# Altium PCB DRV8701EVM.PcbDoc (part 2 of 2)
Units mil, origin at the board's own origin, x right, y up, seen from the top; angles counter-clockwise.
Board outline 3500 x 2200 mil, 2 copper layers (Top Layer, Bottom Layer), stack 64.8 mil thick; 118 components, 65 nets, 313 pads, 397 vias.
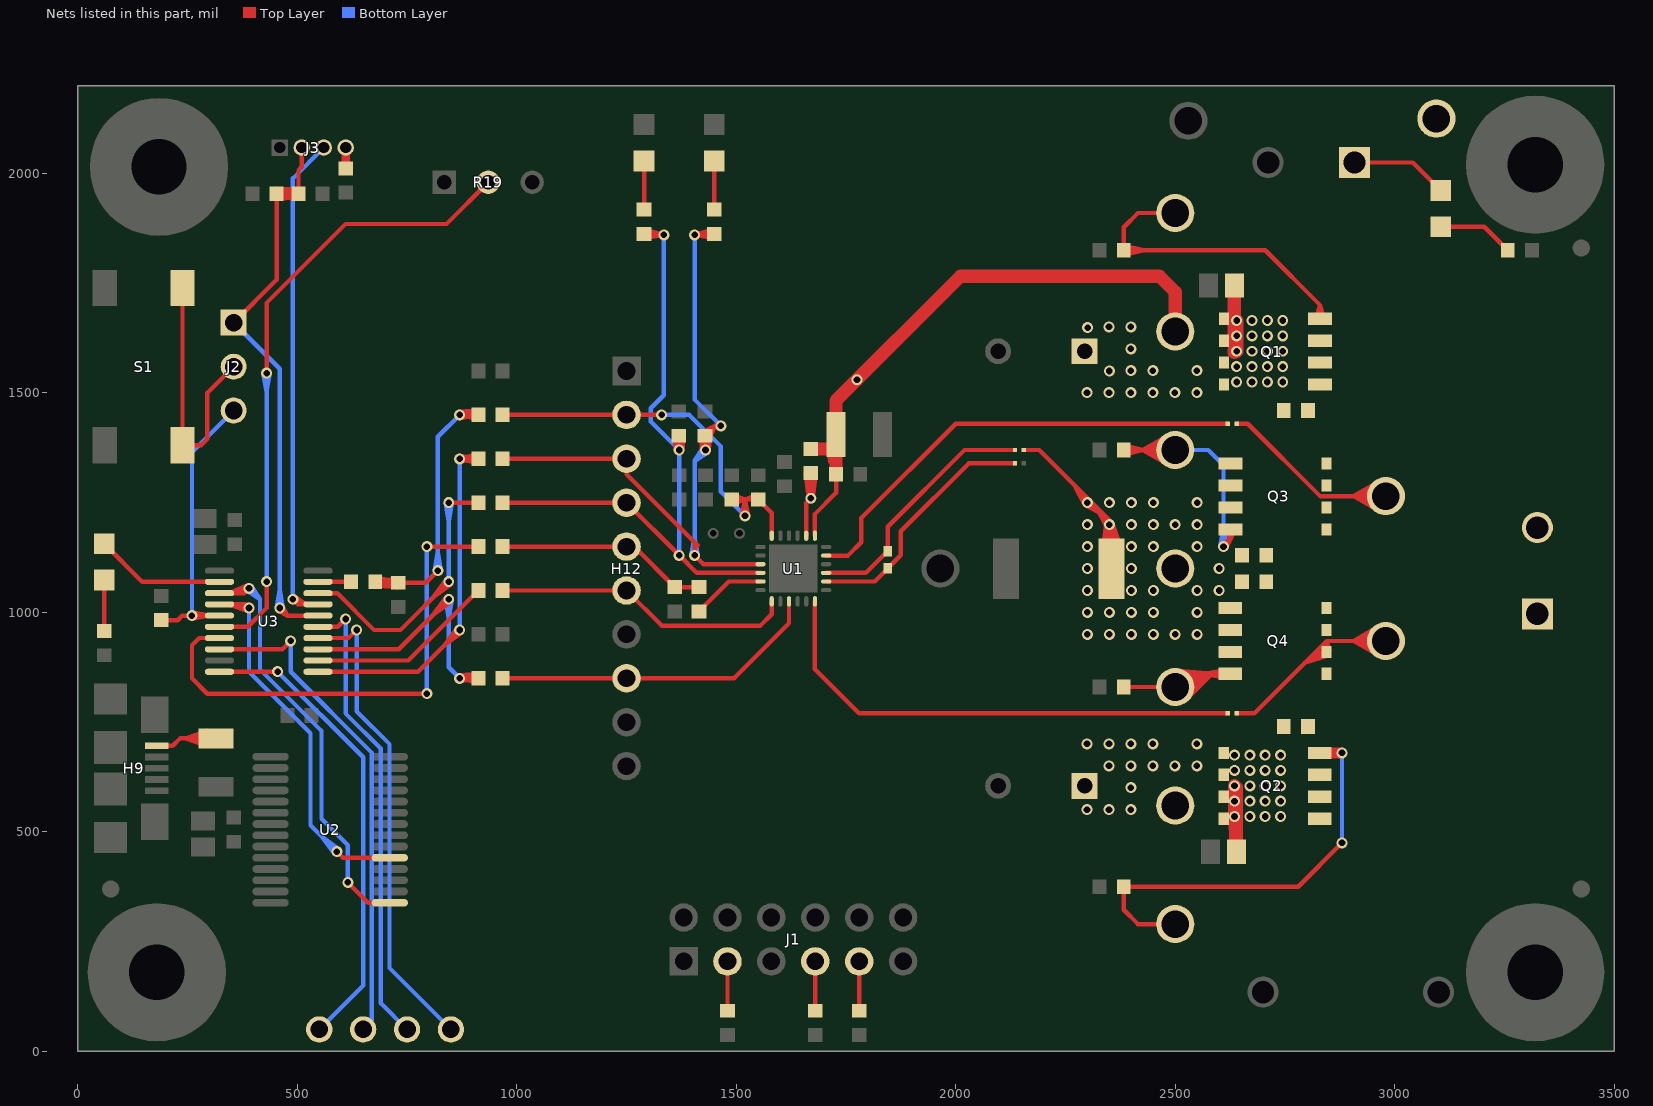
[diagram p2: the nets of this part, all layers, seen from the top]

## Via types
v1: diameter 25, hole 15, Top Layer to Bottom Layer, tented both sides, 392 vias
v2: diameter 20, hole 8, Top Layer to Bottom Layer, 5 vias

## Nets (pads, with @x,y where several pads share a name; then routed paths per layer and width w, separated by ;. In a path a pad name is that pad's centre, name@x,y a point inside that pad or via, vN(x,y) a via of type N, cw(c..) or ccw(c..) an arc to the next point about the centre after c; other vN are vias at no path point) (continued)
NetC13_2: C13.2 C14.2 NT3.1 Q3.1 Q3.2 Q3.3 Q4.1 Q4.2 Q4.3 R9.2 TP12.1 | length 1895.3
  Top Layer w10: NT3.1@2155,1370 2190,1370 2355.08,1204.92 R9.2@2355.08,1100 ; v1@2293.65,1246 2271,1289 ; v1@2296.04,1243.63 2338.22,1221.78 ; v1@2304.92,1255.66 2338.22,1221.78 ; v1@2305.66,1254.93 2271,1289 ; R9.2@2331.08,1144.42 v1@2355.08,1198.9 ; R9.2@2340.66,1141.14 v1@2355.08,1198.9 ; v1@2342.51,1200.29 R9.2@2344.56,1156.78 ; v1@2342.67,1201.59 R9.2@2337.04,1157.96 ; v1@2343.2,1196.83 R9.2@2365.12,1158.7 ; v1@2343.66,1195.99 2320.81,1239.19 ; v1@2343.78,1195.81 R9.2@2371.81,1160.93 ; R9.2@2355.08,1139.37 v1@2355.08,1198.9 ; v1@2355.65,1204.93 2320.81,1239.19 ; v1@2356.83,1203.09 R9.2@2371.81,1160.93 ; v1@2356.95,1197.19 R9.2@2337.04,1157.96 ; v1@2357.24,1201.97 R9.2@2365.12,1158.7 ; v1@2357.33,1198.43 R9.2@2344.56,1156.78 ; R9.2@2369.5,1141.14 v1@2355.08,1198.9 ; R9.2@2379.08,1144.42 v1@2355.08,1198.9 ; 2271,1289 v1(2300,1250) 2338.22,1221.78 ; 2320.81,1239.19 v1(2350,1200) ; R9.2@2337.04,1157.96 v1(2350,1200) ; R9.2@2344.56,1156.78 v1(2350,1200) ; v1(2350,1200) R9.2@2355.08,1156.94 ; v1(2350,1200) R9.2@2371.81,1160.93 ; v1(2350,1200) R9.2@2365.12,1158.7 ; v1(2350,1200) R9.2@2355.08,1156.81 ; R9.2@2355.08,1156.81 2357.5,1200.23 R9.2@2355.08,1156.94 ; R9.2@2355.08,1156.81 2342.65,1198.49 R9.2@2355.08,1156.94
  other v1: 2300,950 2350,950 2400,950 2450,950 2500,950 2550,950 2300,1000 2350,1000 2400,1000 2450,1000 2550,1000 2300,1050 2400,1050 2450,1050 2550,1050 2600,1050 2300,1100 2400,1100 2600,1100 2300,1150 2400,1150 2450,1150 2550,1150 2300,1200 2400,1200 2450,1200 2500,1200 2550,1200 2350,1250 2400,1250 2450,1250 2550,1250
NetD1_2: D1.2 R23.2 | length 116.1
  Top Layer w10: R23.2@60,957.56 D1.2@60,1073.66
NetD2_2: D2.2 R24.2 | length 111.1
  Top Layer w10: R24.2@1450,1917.56 D2.2@1450,2028.66
NetD3_2: D3.2 R25.2 | length 111.1
  Top Layer w10: R25.2@1290,1917.56 D3.2@1290,2028.66
NetD4_2: D4.2 R26.2 | length 174.7
  Top Layer w10: D4.2@3105,1878.66 3203.78,1878.66 R26.2@3257.44,1825
NetF1_1: F1.1 H9.1 | length 421.9
  Top Layer w10: H9.1@180,696.18 216.18,696.18 ; H9.1@198.7,696.18 216.18,696.18 ; F1.1@294.58,695.74 245,713 ; F1.1@294.58,730.26 245,713 ; F1.1@296.96,705.52 245,713 ; F1.1@296.96,720.48 245,713 ; F1.1@297.5,713 245,713 ; F1.1@315,713 233,713 216.18,696.18
NetJ1_3: J1.3 R13.1 | length 112.4
  Top Layer w10: R13.1@1480,92.56 J1.3@1480,205
NetJ1_7: J1.7 R27.2 | length 112.4
  Top Layer w10: R27.2@1680,92.56 J1.7@1680,205
NetJ1_9: J1.9 R28.2 | length 112.4
  Top Layer w10: R28.2@1780,92.56 J1.9@1780,205
NetJ2_2: J2.2 S1.1 S1.2 | length 610.4
  Top Layer w10: S1.1@238.58,1739.13 S1.2@238.58,1380.87 280.87,1380.87 295,1395 295,1500 J2.2@355,1560
NetJ3_4: J3.4 R18.1 | length 94.9
  Top Layer w20: R18.1@610.21,2011.56 J3.4@610.21,2059 R18.1@610.21,2011.56
NetQ1_4: Q1.4 R1.1 TP5.1 | length 867.5
  Top Layer w10: R1.1@2383.82,1814.33 2428.31,1825 R1.1@2383.82,1835.67 ; TP5.1@2500,1910 2415,1910 2382.56,1877.56 R1.1@2382.56,1825 2705,1825 2829.61,1700.39 ; Q1.4@2820.72,1670.38 2829.61,1700.39 ; Q1.4@2829.61,1669.09 2829.61,1700.39 ; Q1.4@2838.49,1670.38 2829.61,1700.39
NetQ2_4: Q2.4 R2.2 TP6.1 | length 1557.5
  Top Layer w10: TP6.1@2500,290 2415,290 2382.56,322.44 R2.2@2382.56,375 2780,375 v1(2880,475) ; Q2.4@2829.3,680 v1(2880,680) ; v1@2877.51,672.93 Q2.4@2843.4,688.91 ; v1@2877.51,687.07 Q2.4@2843.4,671.09 ; v1@2879.25,672.54 Q2.4@2842.33,680 ; v1@2879.25,687.46 Q2.4@2842.33,680 ; v1@2879.34,672.53 Q2.4@2837.5,680 ; v1@2879.34,687.47 Q2.4@2837.5,680 ; v1@2881.04,672.57 Q2.4@2843.4,671.09 ; v1@2881.04,687.43 Q2.4@2843.4,688.91 ; Q2.4@2837.5,680 v1(2880,680) ; Q2.4@2842.33,680 v1(2880,680) ; Q2.4@2842.33,680 v1(2880,680) ; Q2.4@2843.4,671.09 v1(2880,680) ; Q2.4@2843.4,671.09 v1(2880,680) ; Q2.4@2843.4,688.91 v1(2880,680) ; Q2.4@2843.4,688.91 v1(2880,680)
  Bottom Layer w10: v1(2880,475) v1(2880,680)
NetQ3_4: Q3.4 R3.1 TP9.1 | length 1425.2
  Top Layer w10: R3.1@2382.56,1370 TP9.1@2500,1370 2426.5,1370 ; R3.1@2383.82,1359.33 2428.31,1370 R3.1@2383.82,1380.67 ; TP9.1@2489.92,1332.84 2426.5,1370 ; TP9.1@2489.92,1407.16 2426.5,1370 ; TP9.1@2494.47,1342.04 2426.5,1370 ; TP9.1@2494.47,1397.96 2426.5,1370 ; TP9.1@2497.67,1351.65 2426.5,1370 ; TP9.1@2497.67,1388.35 2426.5,1370 ; TP9.1@2499.51,1361.51 2426.5,1370 ; TP9.1@2499.51,1378.49 2426.5,1370 ; v1@2605.65,1156.11 2626,1166 ; v1(2610,1150) 2626,1166 ; v1@2616.11,1145.65 2626,1166 ; Q3.4@2617.19,1187.35 2626,1166 ; Q3.4@2634.81,1187.35 2626,1166 ; 2626,1166 Q3.4@2626,1189.09 2626,1166
  Bottom Layer w10: TP9.1@2500,1370 2575,1370 2610,1335 v1(2610,1150) ; v1@2602.53,1150.66 2610,1192.5 v1@2617.47,1150.66
NetQ4_4: Q4.4 R4.2 TP10.1 | length 1188.7
  Top Layer w10: R4.2@2382.56,830 TP10.1@2500,830 ; TP10.1@2494.81,858.02 2583.81,860 ; TP10.1@2495.17,868.2 2583.81,860 ; TP10.1@2495.61,847.97 2583.81,860 ; TP10.1@2497.52,838.13 2583.81,860 ; TP10.1@2503.24,822.14 2583.81,860 ; TP10.1@2508.01,813.32 2583.81,860 ; TP10.1@2513.78,805.05 2583.81,860 ; TP10.1@2520.51,797.42 2583.81,860 ; Q4.4@2611.75,851.07 2568.69,860 ; Q4.4@2611.75,868.93 2568.69,860 ; Q4.4@2612.67,860 2568.69,860 ; Q4.4@2625.7,860 2530,860 TP10.1@2500,830 ; TP10.1@2500,830 2583.81,860
NetR11_1: R11.1 U3.19 | length 75.4
  Top Layer w10: U3.19@547.2,1069.57 547.64,1070 R11.1@622.44,1070
NetR30_2: R30.2 U1.11 | length 168.4
  Top Layer w10: R30.2@1415,1002.44 1483.03,1070.47 U1.11@1555.2,1070.47
NFAULT: H12.3 R5.2 R14.1 R24.1 U1.9 | length 2607.7
  Top Layer w10: R14.1@967.56,1350 H12.3@1250,1350 1250,1315 1412.42,1152.58 ; 1405,1155 v1(1405,1130) 1425.16,1109.84 U1.9@1555.2,1109.84 ; v1@1422.54,1370.79 R5.2@1429.69,1402.44 ; v1@1422.55,1370.9 R5.2@1430,1401.14 ; v1@1422.69,1368.31 R5.2@1419.1,1400.56 ; v1@1423.21,1373.19 R5.2@1440.3,1400.76 ; R5.2@1423.31,1411.1 1451.26,1425 ; v1@1436.73,1373.32 R5.2@1419.1,1400.56 ; v1@1437.34,1368.46 R5.2@1440.3,1400.76 ; v1@1437.45,1370.9 R5.2@1430,1401.14 ; v1@1437.44,1370.94 R5.2@1429.69,1402.44 ; R5.2@1438.62,1396.46 1451.26,1425 ; R24.1@1447.12,1873.02 v1(1405,1860) ; R24.1@1448.3,1851.72 v1(1405,1860) ; R24.1@1449.02,1862.44 v1(1405,1860) ; R24.1@1450,1862.44 1447.56,1860 v1(1405,1860) ; R5.2@1419.1,1400.56 v1(1430,1370) ; R5.2@1419.1,1400.56 v1(1430,1370) ; R5.2@1429.69,1402.44 v1(1430,1370) ; R5.2@1429.69,1402.44 1451.26,1425 ; R5.2@1429.69,1402.44 v1(1430,1370) ; v1(1430,1370) R5.2@1430,1401.14 ; v1(1430,1370) R5.2@1440.3,1400.76 ; R5.2@1430,1401.14 R5.2@1428.7,1402.44 1451.26,1425 ; 1451.26,1425 v1(1465,1425) ; 1451.26,1425 v1@1462.95,1417.78 ; 1451.26,1425 v1@1462.95,1432.22 ; 1451.26,1425 v1(1465,1425) ; 1451.26,1425 v1@1462.95,1417.78 ; 1451.26,1425 v1@1462.95,1432.22 ; 1451.26,1425 v1(1465,1425) ; 1451.26,1425 v1@1462.95,1417.78 ; 1451.26,1425 v1@1462.95,1432.22 ; 1451.26,1425 v1(1465,1425) ; 1451.26,1425 v1@1462.95,1417.78 ; 1451.26,1425 v1@1462.95,1432.22 ; 1451.26,1425 v1(1465,1425) ; 1451.26,1425 v1@1462.95,1417.78 ; 1451.26,1425 v1@1462.95,1432.22 ; 1451.26,1425 v1(1465,1425)
  Bottom Layer w10: v1@1397.53,1130.66 1405,1172.5 v1@1412.47,1130.66 ; v1(1405,1130) 1405,1345 ; v1(1405,1860) 1405,1485 v1(1465,1425) ; v1@1424.16,1374.71 1405,1345 ; v1@1434.71,1364.16 1405,1345 ; 1405,1345 v1(1430,1370) 1405,1345
NFAULT_MCU: R14.2 U3.11 | length 1271.7
  Top Layer w10: U3.11@547.2,864.84 774.84,864.84 v1(870,960) 836.29,926.29 ; U3.11@573.78,864.84 610.67,864.84 ; v1@864.3,964.87 836.29,926.29 ; v1@874.87,954.3 836.29,926.29 ; R14.2@911.08,1339.34 v1(870,1350) ; R14.2@911.08,1360.66 v1(870,1350) ; v1(870,1350) R14.2@912.44,1350 ; v1(870,1350) R14.2@912.44,1350 ; R14.2@912.44,1350 870.66,1357.47 R14.2@912.44,1350 ; R14.2@912.44,1350 870.66,1342.53 R14.2@912.44,1350
  Bottom Layer w10: v1(870,960) v1(870,1350)
NSLEEP: H12.6 R21.1 U1.13 | length 686.5
  Top Layer w10: R21.1@967.56,1050 H12.6@1250,1050 1330,970 1555,970 1580.79,995.79 U1.13@1580.79,1025.2
NSLEEP_MCU: R21.2 U3.12 | length 468.2
  Top Layer w10: U3.12@547.2,890.43 752.87,890.43 R21.2@912.44,1050 ; U3.12@573.78,890.43 610.67,890.43
OUT1: C8.2 C14.1 H11.1 NT2.2 Q2.1 Q2.2 Q2.3 Q4.5 Q4.6 Q4.7 Q4.8 TP8.1 | length 1299.2
  Top Layer w10: NT2.2@2640,770 2680,770 2845,935 ; Q4.6@2837.79,913.53 2845,935 ; Q4.6@2841.2,913.48 2795.34,885.34 ; Q4.6@2844.3,907.64 2795.34,885.34 ; Q4.6@2844.3,912.36 2845,935 ; Q4.6@2846.67,901.46 2795.34,885.34 ; Q4.6@2850.87,913.13 2845,935 ; TP8.1@2969.92,897.84 2906.5,935 ; TP8.1@2969.92,972.16 2906.5,935 ; TP8.1@2974.47,907.04 2906.5,935 ; TP8.1@2974.47,962.96 2906.5,935 ; TP8.1@2977.67,916.65 2906.5,935 ; TP8.1@2977.67,953.35 2906.5,935 ; TP8.1@2979.51,926.51 2906.5,935 ; TP8.1@2979.51,943.49 2906.5,935 ; 2845,935 TP8.1@2980,935 2906.5,935
OUT2: C7.2 C13.1 H11.2 NT1.2 Q1.1 Q1.2 Q1.3 Q3.5 Q3.6 Q3.7 Q3.8 TP7.1 | length 1069.8
  Top Layer w10: NT1.2@2640,1430 2665,1430 2830,1265 TP7.1@2980,1265 2906.5,1265 ; TP7.1@2969.92,1227.84 2906.5,1265 ; TP7.1@2969.92,1302.16 2906.5,1265 ; TP7.1@2974.47,1237.04 2906.5,1265 ; TP7.1@2974.47,1292.96 2906.5,1265 ; TP7.1@2977.67,1246.65 2906.5,1265 ; TP7.1@2977.67,1283.35 2906.5,1265 ; TP7.1@2979.51,1256.51 2906.5,1265 ; TP7.1@2979.51,1273.49 2906.5,1265
P1.6: TP22.1 U3.14 | length 1094.5
  Top Layer w10: U3.14@547.2,941.61 616.61,941.61 v1(635,960)
  Bottom Layer w10: v1(635,960) 635,775 710,700 710,190 TP22.1@850,50
P1.7: TP23.1 U3.15 | length 1063.2
  Top Layer w10: U3.15@547.2,967.2 592.2,967.2 v1(610,985)
  Bottom Layer w10: v1(610,985) 610,770 690,690 690,110 TP23.1@750,50
P2.0: TP20.1 U3.8 | length 1140
  Top Layer w10: U3.8@322.8,916.02 466.02,916.02 v1(485,935)
  Bottom Layer w10: v1(485,935) 485,865 670,680 670,70 TP20.1@650,50
P2.2: TP21.1 U3.10 | length 1074.5
  Top Layer w10: U3.10@322.8,864.84 454.84,864.84 v1(455,865) v1@460,865
  Bottom Layer w10: v1(455,865) 650,670 650,150 TP21.1@550,50
PH/IN1: H12.8 R29.1 U1.15 | length 754.5
  Top Layer w10: R29.1@967.56,850 H12.8@1250,850 1495,850 1620.16,975.16 U1.15@1620.16,1025.2
PH/IN1_MCU: R29.2 U3.13 | length 1267.2
  Top Layer w10: U3.13@547.2,916.02 731.02,916.02 v1(845,1030) 811.29,996.29 ; U3.13@573.78,916.02 610.67,916.02 ; v1@839.3,1034.87 811.29,996.29 ; v1@849.87,1024.3 811.29,996.29 ; v1@868.76,857.4 R29.2@911.08,860.66 ; v1@872.52,842.94 R29.2@911.08,860.66 ; R29.2@911.08,839.34 v1(870,850) ; v1(870,850) R29.2@912.44,850 ; v1(870,850) R29.2@911.08,860.66 ; v1(870,850) R29.2@912.44,850 ; R29.2@912.44,850 870.66,857.47 R29.2@912.44,850 ; R29.2@912.44,850 870.66,842.53 R29.2@912.44,850
  Bottom Layer w10: v1@837.53,1029.34 845,987.5 ; v1@852.47,1029.34 845,987.5 ; v1(870,850) 845,875 v1(845,1030) 845,987.5
POT: R19.2 U3.6 | length 1603.2
  Top Layer w10: U3.6@322.8,967.2 387.2,967.2 430,1010 v1(430,1070) ; U3.6@349.37,967.2 386.26,967.2 ; v1(430,1545) 430,1705 610,1885 840,1885 R19.2@935,1980
  Bottom Layer w10: v1@422.53,1544.34 430,1502.5 ; v1(430,1070) v1(430,1545) 430,1502.5 ; v1@437.47,1544.34 430,1502.5
PUSH: J2.3 R15.1 U3.5 | length 837.3
  Top Layer w10: R15.1@190,982.44 227.44,982.44 237.8,992.8 v1(260,992.8) ; v1@260.66,985.32 302.5,992.8 v1@260.66,1000.27 ; v1@260.78,985.34 U3.5@296.22,992.8 ; v1@260.78,1000.26 U3.5@296.22,992.8 ; U3.5@322.8,992.8 v1(260,992.8) ; v1(260,992.8) U3.5@296.22,992.8
  Bottom Layer w10: v1(260,992.8) 260,1365 J2.3@355,1460
RESET: C22.1 J2.1 J3.2 R17.1 U3.16 | length 2092.6
  Top Layer w10: J2.1@355,1660 452.77,1757.77 C22.1@452.77,1954 ; C22.1@451.95,1942.3 R17.1@497.86,1944.18 ; C22.1@451.95,1965.71 R17.1@497.86,1963.83 ; C22.1@452.77,1953.02 R17.1@497.86,1944.18 ; C22.1@452.77,1954.99 R17.1@497.86,1963.83 ; v1@455.58,1003.94 477.2,992.8 ; C22.1@456.05,1944.76 R17.1@497.86,1963.83 ; C22.1@456.05,1963.25 R17.1@497.86,1944.18 ; v1(460,1010) 477.2,992.8 ; v1@466.06,1014.42 477.2,992.8 ; 483.74,992.8 U3.16@520.63,992.8 ; R17.1@501.39,1943.33 C22.1@456.9,1954 ; R17.1@501.39,1964.68 C22.1@456.9,1954 ; J3.2@510.21,2059 510.21,2015.21 502.65,2007.65 R17.1@502.65,1954 ; U3.16@547.2,992.8 477.2,992.8 ; C22.1@452.77,1954 R17.1@502.65,1954 ; C22.1@452.77,1954 R17.1@498.52,1954 ; C22.1@456.9,1954 R17.1@502.65,1954 ; R17.1@498.52,1954 454.03,1943.33 R17.1@498.52,1954 ; R17.1@498.52,1954 454.03,1964.68 R17.1@498.52,1954
  Bottom Layer w10: J2.1@355,1660 460,1555 v1(460,1010) ; v1@452.53,1010.66 460,1052.5 v1@467.47,1010.66
RX: U2.5 U3.4 | length 1315.1
  Top Layer w10: U3.4@322.8,1018.39 v1@381.61,1018.39 ; v1@387.83,1002.82 U3.4@349.37,1018.39 ; v1@388.08,1002.75 U3.4@343.64,1018.39 ; v1@390.74,1017.46 U3.4@343.64,1018.39 ; v1@390.85,1017.45 U3.4@349.37,1018.39 ; v1(590,455) 603.98,441.02 U2.5@710.83,441.02 ; 639.49,441.02 U2.5@678.35,441.02 ; U3.4@343.64,1018.39 v1(390,1010) ; U3.4@349.37,1018.39 v1@381.61,1018.39 ; U3.4@349.37,1018.39 v1(390,1010) ; v1@381.61,1018.39 v1(390,1010)
  Bottom Layer w10: v1(390,1010) 390,865 530,725 530,515 v1(590,455) 556.29,488.71 ; v1@584.3,450.13 556.29,488.71 ; v1@594.87,460.7 556.29,488.71
S_N: C17.2 NT4.1 U1.20 | length 609.1
  Top Layer w10: U1.20@1704.8,1070.47 1815.47,1070.47 1875,1130 1875,1185 2030,1340 NT4.1@2135,1340 2100,1340
S_P: C17.1 NT3.2 U1.21 | length 613.4
  Top Layer w10: U1.21@1704.8,1090 1795,1090 1845,1140 1845,1195 2020,1370 NT3.2@2135,1370 2100,1370
SH1: NT2.1 U1.18 | length 1171.9
  Top Layer w10: U1.18@1679.21,1025.2 1679.21,870.79 1780,770 NT2.1@2620,770 2585,770
SH2: NT1.1 U1.23 | length 1106.9
  Top Layer w10: U1.23@1704.8,1129.53 1754.53,1129.53 1785,1160 1785,1215 2000,1430 NT1.1@2620,1430 2585,1430
SNSOUT: H12.4 R7.2 R16.1 R25.1 U1.10 | length 2053.5
  Top Layer w10: R16.1@967.56,1250 H12.4@1250,1250 v1(1370,1130) 1409.69,1090.31 U1.10@1555.2,1090.31 ; R25.1@1290,1862.44 1292.44,1860 v1(1335,1860) ; R25.1@1290.98,1862.44 v1(1335,1860) ; R25.1@1291.7,1851.72 v1(1335,1860) ; R25.1@1292.88,1873.02 v1(1335,1860) ; v1@1362.54,1370.79 R7.2@1369.69,1402.44 ; v1@1362.55,1370.9 R7.2@1370,1401.14 ; v1@1362.69,1368.31 R7.2@1359.1,1400.56 ; v1@1363.21,1373.19 R7.2@1380.3,1400.76 ; R7.2@1368.7,1402.44 R7.2@1370,1401.14 ; v1@1376.73,1373.32 R7.2@1359.1,1400.56 ; v1@1377.34,1368.46 R7.2@1380.3,1400.76 ; v1@1377.45,1370.9 R7.2@1370,1401.14 ; v1@1377.44,1370.94 R7.2@1369.69,1402.44 ; R7.2@1359.1,1400.56 v1(1370,1370) ; R7.2@1359.1,1400.56 v1(1370,1370) ; R7.2@1369.69,1402.44 v1(1370,1370) ; R7.2@1369.69,1402.44 v1(1370,1370) ; v1(1370,1370) R7.2@1370,1401.14 ; v1(1370,1370) R7.2@1380.3,1400.76
  Bottom Layer w10: v1(1335,1860) 1335,1495 1305,1465 1305,1435 v1(1370,1370) v1(1370,1130)
SNSOUT_MCU: R16.2 U3.18 | length 913.4
  Top Layer w10: U3.18@547.2,1043.98 591.02,1043.98 ; U3.18@573.78,1043.98 591.02,1043.98 ; v1@839.3,1074.87 811.29,1036.29 ; v1(845,1250) R16.2@912.44,1250 ; v1@849.87,1064.3 811.29,1036.29 ; 591.02,1043.98 675,960 735,960 v1(845,1070) 811.29,1036.29
  Bottom Layer w10: v1@837.53,1249.34 845,1207.5 ; v1(845,1070) v1(845,1250) 845,1207.5 ; v1@852.47,1249.34 845,1207.5
SO: H12.5 R20.1 R30.1 R31.1 | length 485.7
  Top Layer w10: R20.1@967.56,1150 H12.5@1250,1150 1267.56,1150 R31.1@1360,1057.56 R30.1@1415,1057.56
SO_MCU: R20.2 U3.7 | length 1166.2
  Top Layer w10: U3.7@296.22,941.61 276.61,941.61 ; U3.7@322.8,941.61 276.61,941.61 ; v1(795,815) 295,815 260,850 260,925 276.61,941.61 ; v1(795,1150) R20.2@912.44,1150
  Bottom Layer w10: v1(795,815) v1(795,1150)
STATUS: D1.1 U3.2 | length 335.6
  Top Layer w10: D1.1@60,1156.34 146.77,1069.57 U3.2@322.8,1069.57 ; 259.33,1069.57 U3.2@296.22,1069.57
TEST: J3.3 U3.17 | length 1237.4
  Top Layer w10: v1@488.16,1022.73 U3.17@520.63,1018.39 ; v1@493.44,1036.66 U3.17@520.63,1018.39 ; U3.17@547.2,1018.39 501.61,1018.39 ; 501.61,1018.39 v1(490,1030) U3.17@520.63,1018.39 ; 501.61,1018.39 U3.17@520.63,1018.39
  Bottom Layer w10: v1(490,1030) 490,1988.8 J3.3@560.21,2059
TX: U2.1 U3.3 | length 1333.7
  Top Layer w10: U3.3@322.8,1043.98 378.98,1043.98 ; v1@387.4,1062.03 U3.3@349.37,1043.98 ; v1@387.65,1062.12 U3.3@344.61,1043.98 ; v1@391.18,1047.59 U3.3@344.61,1043.98 ; v1@391.31,1047.62 U3.3@349.37,1043.98 ; v1(615,385) 661.34,338.66 ; U2.1@678.35,338.66 661.34,338.66 ; U2.1@710.83,338.66 661.34,338.66 ; U3.3@344.61,1043.98 v1(390,1055) ; U3.3@349.37,1043.98 378.98,1043.98 ; U3.3@349.37,1043.98 v1(390,1055) ; 378.98,1043.98 v1(390,1055)
  Bottom Layer w10: v1@385.29,1049.16 415,1030 ; v1(390,1055) 415,1030 ; v1@395.84,1059.71 415,1030 ; v1(615,385) 615,470 555,530 555,730 415,870 415,1030
VCP: C9.1 TP13.1 U1.2 | length 565.6
  Top Layer w10: C9.1@1658.27,1317.28 TP13.1@1664.34,1270.78 ; C9.1@1659.33,1316.18 TP13.1@1670,1271.69 ; U1.2@1659.53,1174.8 1659.53,1249.53 TP13.1@1670,1260 C9.1@1670,1317.44 TP13.1@1670,1271.69 ; C9.1@1660.48,1315.15 TP13.1@1675.66,1270.78 ; C9.1@1669.02,1317.44 TP13.1@1664.34,1270.78 ; C9.1@1670.98,1317.44 TP13.1@1675.66,1270.78 ; C9.1@1679.52,1315.15 TP13.1@1664.34,1270.78 ; C9.1@1680.67,1316.18 TP13.1@1670,1271.69 ; C9.1@1681.73,1317.28 TP13.1@1675.66,1270.78
VM: C1.1 C2.1 C5.1 C6.1 C7.1 C8.1 C9.2 C10.1 C11.1 D4.1 H10.1 Q1.5 Q1.6 Q1.7 Q1.8 Q2.5 Q2.6 Q2.7 Q2.8 TP1.1 TP2.1 TP3.1 TP11.1 U1.1 | length 4268.7
  Top Layer w10: U1.1@1679.21,1174.8 1679.21,1224.21 1727.44,1272.44 C11.1@1727.44,1315 ; C10.1@1710.32,1377.51 1714.41,1342.56 ; C10.1@1720.43,1377.23 1714.41,1342.56 ; C10.1@1726.85,1355 1714.41,1342.56 ; C10.1@1726.85,1375.47 1714.41,1342.56 ; C10.1@1732.82,1372.54 1714.41,1342.56 ; C10.1@1740.59,1366.06 1714.41,1342.56 ; H10.1@2908.43,2025 3041.34,2025 D4.1@3105,1961.34
  Top Layer w30: C9.2@1670,1372.56 1714.41,1372.56 C9.2@1670.98,1372.56 ; C10.1@1726.85,1434.53 1726.85,1481.85 ; TP11.1@1775,1530 1726.85,1481.85 ; TP2.1@2500,1640 2500,1730 2464.17,1765.83 2010.83,1765.83 1726.85,1481.85 ; C5.1@2634.53,1739.09 v1@2634.53,1627.44 ; C10.1@1726.85,1355 1726.85,1315.59 1726.85,1375.47 1727.44,1315.98 C10.1@1726.85,1355 ; C10.1@1726.85,1355 C10.1@1726.85,1405 1726.85,1481.85 ; v1@2634.53,1592.62 v1(2640,1630) ; v1@2634.53,1592.62 v1(2640,1630) ; v1@2634.53,1592.62 v1(2640,1665) ; v1@2634.53,1592.62 v1(2640,1665) ; v1@2634.53,1627.44 v1(2640,1665) ; v1@2634.53,1627.44 v1(2640,1665) ; v1(2635,535) v1@2639.53,601.17 ; v1(2635,535) C6.1@2639.53,455 v1@2639.53,601.17 ; v1(2635,535) 2639.53,572.56 2639.53,460.91 v1(2635,535) ; v1(2635,535) 2639.53,501.56 ; v1(2635,535) v1(2635,605) ; v1(2635,535) 2639.53,466.86 v1(2635,570) ; v1(2635,535) v1(2635,570) ; v1(2635,535) 2639.53,466.98 v1(2635,570) ; v1(2635,535) v1(2635,570) ; v1(2635,535) 2639.53,501.56 ; v1(2635,535) v1(2635,570) ; v1(2635,570) v1@2639.53,601.17 ; v1(2635,570) 2639.53,501.56 ; v1(2635,570) v1(2635,605) ; v1(2635,605) 2639.53,501.56 ; v1(2640,1595) v1(2640,1630) ; v1(2640,1595) v1(2640,1630) ; v1(2640,1595) v1(2640,1665) ; v1(2640,1595) v1(2640,1665) ; v1(2640,1630) v1(2640,1665) ; v1(2640,1630) v1(2640,1665) ; v1(2640,1630) v1(2640,1665) ; v1(2640,1630) v1(2640,1665) ; v1(2640,1630) v1(2640,1665) ; v1(2640,1630) v1(2640,1665)
  other v1: 2670,535 2705,535 2740,535 2299.12,550.63 2349.12,550.63 2399.12,550.63 2670,570 2705,570 2740,570 2399.12,600.63 2670,605 2705,605 2740,605 2635,640 2670,640 2705,640 2740,640 2349.12,650.63 2399.12,650.63 2449.12,650.63 2499.12,650.63 2549.12,650.63 2635,675 2670,675 2705,675 2740,675 2299.12,700.63 2349.12,700.63 2399.12,700.63 2449.12,700.63 2549.12,700.63 2299.12,1500.63 2349.12,1500.63 2399.12,1500.63 2449.12,1500.63 2499.12,1500.63 2549.12,1500.63 2640,1525 2675,1525 2710,1525 2745,1525 2350,1550 2399.12,1550.63 2449.12,1550.63 2549.12,1550.63 2640,1560 2675,1560 2710,1560 2745,1560 2675,1595 2710,1595 2745,1595 2399.12,1600.63 2675,1630 2710,1630 2745,1630 2300.54,1648.78 2349.12,1650.63 2399.12,1650.63 2675,1665 2710,1665 2745,1665
VREF: H12.2 R6.1 R8.2 R12.1 U1.6 | length 1091.9
  Top Layer w10: R12.1@967.56,1450 H12.2@1250,1450 v1(1330,1450) ; R6.1@1490,1257.44 1520,1257.44 ; R6.1@1490.98,1257.44 1520,1257.44 ; R6.1@1492.97,1246.88 1520,1257.44 ; R6.1@1492.97,1268 1520,1257.44 ; v1@1512.54,1220.75 1520,1257.44 ; v1(1520,1220) 1520,1257.44 ; v1@1527.46,1220.75 1520,1257.44 ; R8.2@1547.03,1268 1520,1257.44 ; U1.6@1580.79,1174.8 1580.79,1226.65 R8.2@1550,1257.44 1520,1257.44
  Bottom Layer w10: v1(1330,1450) 1393.11,1450 1465,1378.11 1465,1275 v1(1520,1220)
VREF_MCU: C19.1 R11.2 R12.2 | length 1408.4
  Top Layer w10: R11.2@677.56,1070 727.56,1070 C19.1@730,1067.56 792.56,1067.56 v1(820,1095) ; R11.2@678.82,1059.33 723.31,1070 R11.2@678.82,1080.67 ; C19.1@726.13,1077.91 R11.2@683.17,1060.37 ; C19.1@727.19,1056.97 R11.2@683.17,1070 ; C19.1@728.33,1078.28 R11.2@683.17,1070 ; C19.1@729.44,1056.82 R11.2@683.17,1060.37 ; v1@868.76,1457.4 R12.2@911.08,1460.66 ; v1@872.52,1442.94 R12.2@911.08,1460.66 ; R12.2@911.08,1439.34 v1(870,1450) ; R11.2@683.17,1060.37 729.02,1067.56 R11.2@683.17,1070 ; v1(870,1450) R12.2@912.44,1450 ; v1(870,1450) R12.2@911.08,1460.66 ; v1(870,1450) R12.2@912.44,1450 ; R12.2@912.44,1450 870.66,1457.47 R12.2@912.44,1450 ; R12.2@912.44,1450 870.66,1442.53 R12.2@912.44,1450
  Bottom Layer w10: v1@812.53,1095.66 820,1137.5 v1@827.47,1095.66 ; v1(820,1095) 820,1400 v1(870,1450)
pads on no net: FID1.1 FID2.1 FID3.1 H1.1 H2.1 H3.1 H4.1 H5.0 H6.0 H7.0 H8.0 H9.4 J1.5 SH-J1.0 SH-J2.0 U2.2 U2.3 U2.6 U2.8 U2.9 U2.10 U2.11 U2.12 U2.13 U2.14 U2.19 U2.22 U2.23 U2.24 U2.27 U2.28

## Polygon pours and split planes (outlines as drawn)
GND on Top Layer "TOP_GND_PLN" (solid, remove dead copper, pour order 23): 0,2200 3500,2200 3500,0 0,0
VM on Top Layer "VM1" (solid, remove dead copper, pour order 21): 2755,1455 2755,1495 2770,1495 2770,1700 2250,1700 2250,1455
VM on Top Layer "VM2" (solid, remove dead copper, pour order 22): 2760,745 2770,735 2770,500 2250,500 2250,745
NetC13_2 on Top Layer "SP" (solid, remove dead copper, pour order 14): 2660,1365 2660,1220 2580,1220 2580,1120 2640,1120 2640,1145 2665,1145 2665,890 2250,890 2250,1310 2540,1310 2595,1365
GND on Top Layer "SN" (solid, remove dead copper, pour order 17): 2200,890 2200,1310 2035,1310 1900,1175 1900,1025 2035,890
GND on Top Layer "GND1" (solid, remove dead copper, pour order 19): 2200,1700 2200,1455 1900,1455 1900,1550 2050,1700
GND on Top Layer "GND2" (solid, remove dead copper, pour order 18): 2200,500 2200,745 1900,745 1900,650 2050,500
VM on Bottom Layer "VM" (solid, pour order 15): 2880,1610 2880,720 2850,690 2850,500 2250,500 2250,745 2540,745 2640,845 2640,1355 2540,1455 2250,1455 2250,1700 2290,1740 2630.59,1740 2830,1940 2830,2170 3145,2170 3145,1875
GND on Bottom Layer "GND" (solid, remove dead copper, pour order 20): 2200,500 1900,500 1900,1895 2175,2170 2800,2170 2800,1950 2700,1850 2290,1850 2200,1760
NetC13_2 on Bottom Layer "SP" (solid, remove dead copper, pour order 16): 2250,1400 2370,1400 2460,1310 2580,1310 2580,890 2460,890 2370,800 2250,800
GND on Bottom Layer "BOT_GND_PLN" (solid, remove dead copper, pour order 24): 0,2200 3500,2200 3500,0 0,0

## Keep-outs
Keep-Out Layer:
  the board outline again, w10
  text ".Layer_Name" at 577,-858.49 h60

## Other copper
Top Layer:
  region net 5V_USB: 275,625 355,625 355,600 370,568 390,555 410,550 410,535 260,535 260,545 275,600
  region net OUT2: 2690,1110 3425,1110 3425,1325 3050,1700 2870,1700 2870,1640 2790,1640 2790,1455 2690,1355
  region net OUT1: 2690,1090 3425,1090 3425,875 3050,500 2790,500 2790,650 2905,650 2905,710 2825,710 2690,845
  text ".Layer_Name" at 577,-858.49 h60
Bottom Layer:
  text "MADE IN U.S." at 2610,46.5 h60
  text "TI" at 1567,45 h60
  text ".CopyrightYear" at 1813,45 h60
  text "©" at 1920,41.48 h105
  text ".Layer_Name" at 577,-858.49 h60

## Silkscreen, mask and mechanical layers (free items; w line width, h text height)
Top Overlay:
  lines w10: 1330,970 1870,970 1870,1560 1330,1560 1330,970 ; 1350,400 1350,685 1915,685 1915,400 1350,400
  text "SNSOUT" at 1345,2130 h40 r270
  text "nFAULT" at 1505,2130 h40 r270
  text ".PRJ_Number" at 1610,2110 h60
  text ".PCB_Rev" at 2270,2110 h60
  text "VM" at 3060,2000 h40
  text "GND" at 2475,1995 h40
  text "POT" at 880,1830 h40
  text "GH2" at 2450,1785 h40
  text "GND" at 2685,1775 h40
  text "VM" at 2855,1775 h40
  text "RESET" at 425,1645 h40
  text "DRV8701" at 1470,1580 h40
  text "3.3V" at 1065,1535 h30
  text "VM" at 2470,1515 h40
  text "PUSH" at 425,1445 h40
  text "VREF" at 1060,1435 h30
  text "nFAULT" at 1000,1335 h30
  text "OUT2" at 3070,1295 h40 r270
  text "GL2" at 2445,1245 h40
  text "SNSOUT" at 1000,1235 h30
  text "STATUS" at 115,1205 h40 r270
  text "SO" at 1120,1135 h30
  text "OUT1" at 3070,1040 h40 r270
  text "nSLEEP" at 1000,1035 h30
  text "SP" at 2470,975 h40
  text "SN" at 1935,970 h40
  text "EN/IN2" at 1005,935 h30
  text "PH/IN1" at 1015,835 h30
  text "GND" at 1090,735 h30
  text "SRC/SNK (mA)" at 1930,715 h30 r270
  text "GL1" at 2455,705 h40
  text "6.0/12.5" at 1865,650 h30 r270
  text "150/300" at 1470,640 h30 r270
  text "100/200" at 1570,640 h30 r270
  text "12.5/25" at 1770,640 h30 r270
  text "GND" at 1090,635 h30
  text "25/50" at 1370,615 h30 r270
  text "25/50" at 1670,615 h30 r270
  text "VM" at 2470,435 h40
  text "GND" at 2855,200 h40
  text "GH1" at 2455,165 h40
  text "P2.2" at 565,100 h30 r90
  text "P2.0" at 665,100 h30 r90
  text "P1.7" at 765,100 h30 r90
  text "P1.6" at 865,100 h30 r90
  text ".Layer_Name" at 577,-858.49 h60
Bottom Overlay:
  text ".Layer_Name" at 577,-858.49 h60
Top Paste:
  text ".Layer_Name" at 577,-858.49 h60
Bottom Paste:
  text ".Layer_Name" at 577,-858.49 h60
Top Solder:
  text ".Layer_Name" at 577,-858.49 h60
  text ".Layer_Name" at 577,-858.49 h60
Bottom Solder:
  text ".Layer_Name" at 577,-858.49 h60
Drill Guide:
  text ".Layer_Name" at 577,-858.49 h60
M1 Board Outline:
  the board outline again, w10
  text ".Layer_Name" at 577,-858.49 h60
M2 Board Dimensions:
  rectangle: 124.5,-410.5 499.5,-285.5
  rectangle: -0.5,-285.5 124.5,-160.5
  lines w7: -0.5,-285.5 999.5,-285.5 ; 124.5,-410.5 124.5,-160.5 ; 249.5,-410.5 249.5,-160.5 ; 499.5,-410.5 499.5,-160.5 ; 749.5,-410.5 749.5,-160.5 ; -0.5,-410.5 -0.5,-160.5 999.5,-160.5 999.5,-410.5 -0.5,-410.5
  lines w10: -0.5,-475.5 -0.5,-455.5 ; 59.5,-485.5 -0.5,-465.5 ; 59.5,-445.5 -0.5,-465.5 ; 223.58,-465.5 -0.5,-465.5 ; 775.42,-465.5 999.5,-465.5 ; 939.5,-485.5 999.5,-465.5 ; 939.5,-445.5 999.5,-465.5 ; 999.5,-475.5 999.5,-455.5
  text "1000 (mil)" at 233.58,-501.49 h60
  text ".Layer_Name" at 577,-858.49 h60
M3 3D STEP Top:
  text ".Layer_Name" at 577,-858.49 h60
M4 3D STEP Bottom:
  text ".Layer_Name" at 577,-858.49 h60
M5 Assembly Top:
  lines w10: -292,-930.17 6308,-930.17 ; -292,-726.83 6310,-726.83 ; -292,-523.5 -292,-1133.5 3713,-1133.5 6310,-1133.5 6310,-523.5 -291.5,-523.5 -291.5,-1133.5 1284,-1133.5 ; 2173,-1133.5 2173,-523.5 ; 3440,-726.83 3440,-523.5 ; 4280,-726.83 4280,-523.5 ; 4902,-1140 4902,-937.17
  text "COMPONENTS MARKED 'DNP' SHOULD NOT BE POPULATED." at 1153.5,-318.5 h60
  text "ASSEMBLY VARIANT:" at 1153,-434 h60
  text ".VariantName" at 2189,-434 h60
  text "PCB VIEWED FROM TOP SIDE" at -228.5,-655.67 h60
  text "BOARD #:" at 2248,-655.67 h60
  text ".PRJ_Number" at 2793.5,-655.67 h60
  text "REV:" at 3638,-655.67 h60
  text ".PCB_Rev" at 3929.5,-655.67 h60
  text "SVN REV:" at 4476,-655.67 h60
  text ".VersionControl_RevNumber" at 4982,-655.67 h60
  text "IGNORE ->" at -228.5,-858.49 h60
  text "PLOT NAME =" at -228.5,-1064.34 h60
  text ".plot_File_Name" at 577,-1064.34 h60
  text "GENERATED    :" at 2250,-1064.34 h60
  text ".Print_Date" at 3119.5,-1064.34 h60
  text ".Print_Time" at 3848.5,-1064.34 h60
  text "TEXAS INSTRUMENTS" at 5113,-1064.34 h60
M6 Assembly Bottom:
  lines w10: -292.5,-727.33 6309.5,-727.33 ; -290.5,-930.67 6309.5,-930.67 ; 1115.5,-1140.5 1115.5,-937.67 ; 1737.5,-727.33 1737.5,-524 ; 2577.5,-727.33 2577.5,-524 ; 3844.5,-1134 3844.5,-524 ; 4733.5,-1134 6309,-1134 6309,-524 -292.5,-524 -292.5,-1134 2304.5,-1134 6309.5,-1134 6309.5,-524
  text "COMPONENTS MARKED 'DNP' SHOULD NOT BE POPULATED." at 6102,-318 h60
  text ".VariantName" at 5058,-434 h60
  text "ASSEMBLY VARIANT:" at 6097,-434 h60
  text ".VersionControl_RevNumber" at 1035.5,-656.17 h60
  text "SVN REV:" at 1541.5,-656.17 h60
  text ".PCB_Rev" at 2088,-656.17 h60
  text "REV:" at 2379.5,-656.17 h60
  text ".PRJ_Number" at 3224,-656.17 h60
  text "BOARD #:" at 3769.5,-656.17 h60
  text "PCB VIEWED FROM BOTTOM SIDE" at 6246,-656.17 h60
  text "IGNORE ->" at 2547.85,-858.49 h60
  text "TEXAS INSTRUMENTS" at 904.5,-1064.84 h60
  text ".Print_Time" at 2169,-1064.84 h60
  text ".Print_Date" at 2898,-1064.84 h60
  text "GENERATED    :" at 3767.5,-1064.84 h60
  text ".plot_File_Name" at 5440.5,-1064.84 h60
  text "PLOT NAME =" at 6246,-1064.84 h60
M9 Title Sheet:
  drawing of 57 lines, arcs and shapes, not listed
  text "1" at 739.84,8036.5 h70
  text "2" at 3235.5,8036.5 h70
  text "3" at 5724.84,8036.5 h70
  text "4" at 8231.51,8036.5 h70
  text "5" at 10730.5,8036.5 h70
  text "6" at 13235.5,8036.5 h70
  text "A" at -416.5,6893.5 h70
  text "A" at 14383.5,6893.5 h70
  text "B" at -416.5,4513.5 h70
  text "B" at 14383.5,4513.5 h70
  text "C" at -416.5,2138.5 h70
  text "C" at 14383.5,2138.5 h70
  text "PROJECT TITLE:" at 11343.5,277.5 h45
  text ".PRJ_Title" at 11393.5,144.17 h70
  text "DESIGNED FOR:" at 11343.5,-23.5 h45
  text ".PRJ_Customer" at 11393.5,-163.5 h70
  text "D" at -416.5,-231.5 h70
  text "D" at 14383.5,-231.5 h70
  text "FILE NAME:" at 11343.5,-323.5 h45
  text ".PCB_File_Name_No_Path" at 11393.5,-443.5 h70
  text "Texas Instruments (TI) and/or its licensors do not warrant the accuracy or completeness of this specification" at 6374,-605.34 h45
  text "ENGINEER:" at 11343.5,-613.5 h45
  text "LAYOUT BY:" at 12848.5,-613.5 h45
  text "or any information contained therein. TI and/or its licensors do not warrant that this design will meet" at 6329.01,-718 h45
  text ".PRJ_Engineer" at 11393.5,-768.49 h70
  text ".PCB_Layout" at 12899,-768.49 h70
  text "the specifications, will be suitable for your application or fit for any particular purpose, or will operate in" at 6329.01,-830.67 h45
  text ".Layer_Name" at 577,-858.49 h60
  text "ALTIUM DESIGNER VERSION:" at 12848.5,-923.5 h45
  text "an implementation. TI and/or its licensors do not warrant that the design is production worthy. You should" at 6329.01,-943.33 h45
  text "completely validate and test your design implementation to confirm the system functionality for your application." at 6374,-1056 h45
  text ".print_Scale" at 11393.5,-1056.83 h70
  text ".Application_BuildNumber" at 12899,-1056.83 h70
  text "1" at 739.84,-1263.5 h70
  text "2" at 3235.5,-1263.5 h70
  text "3" at 5724.84,-1263.5 h70
  text "4" at 8231.51,-1263.5 h70
  text "5" at 10730.5,-1263.5 h70
  text "6" at 13235.5,-1263.5 h70
M10 Fab Notes:
  drawing of 212 lines, arcs and shapes, not listed
  text "DESIGN INFORMATION" at 12381.02,6810 h60
  text "(REFER ALSO ARRAY/PANEL PROFILING INFORMATION)" at 12019.46,6648.29 h60
  text "BOARD SIZE" at 11333.46,6644 h60
  text "3500MIL" at 11795.78,6516.18 h60
  text "X" at 12301.46,6516.18 h60
  text "2200MIL" at 12532.78,6516.18 h60
  text "Number of Layers :" at 11736.46,6319 h60
  text "2" at 12831.27,6309 h60
  text "MIN. TRACK WIDTH:" at 11736.46,6180 h60
  text "8" at 12832.7,6180 h60
  text "MIL" at 12987.46,6180 h60
  text "MIN. CLEARANCE:" at 11736.46,6048 h60
  text "8" at 12832.7,6048 h60
  text "MIL" at 12987.46,6048 h60
  text "MIN. VIA PAD SIZE:" at 11736.46,5916 h60
  text "24" at 12802.71,5916 h60
  text "MIL" at 12987.46,5916 h60
  text "0.05mm (2MIL)" at 12431.46,5774.29 h60
  text "MINIMUM ANNULAR RING" at 11407.23,5770 h60
  text "EXTERNAL" at 13139.46,5770 h60
  text "PER" at 11607.23,5652 h60
  text "IPC-D-275 CLASS 2 LEVEL C" at 11827.23,5652 h60
  text "MIL, HOLES" at 13315.46,5539.71 h60
  text "+/-" at 12923,5539 h60
  text "+/-" at 13777,5539 h60
  text "REGISTRATION TOLERANCES:" at 11407.23,5534 h60
  text "METAL" at 12607,5534 h60
  text "5" at 13183.2,5534 h60
  text "3" at 14016.2,5534 h60
  text "MIL" at 14132.46,5534 h60
  text "MATERIAL:" at 11332.46,5324.54 h60
  text "FR-4 High Tg" at 12318.9,5184.21 h60
  text "FR-408" at 11753.46,5175.64 h60
  text "X" at 12165.46,5175.64 h60
  text "OTHER" at 13241.46,5175.64 h60
  text "62 MIL (1.6mm) +/-10%" at 12073.56,5012.92 h60
  text "THICKNESS:" at 11407.23,5008.64 h60
  text "X" at 11945.4,5008.64 h60
  text "OTHER" at 13358.46,5008.64 h60
  text "TOLERANCE:" at 11407.23,4850.64 h60
  text "X" at 12246.53,4850.64 h60
  text "ANSI IPC-6012 TYPE 3 CLASS 2" at 12433.48,4850.64 h60
  text "OTHER +/-" at 12433.46,4694.64 h60
  text "BOW & TWIST:" at 11407.23,4537.64 h60
  text "X" at 12246.53,4537.64 h60
  text "ANSI IPC-6012 TYPE 3 CLASS 2" at 12433.48,4537.64 h60
  text "OTHER +/-" at 12433.46,4379.13 h60
  text "COPPER THICKNESS (FINISHED):" at 11332.46,4243.64 h60
  text "1.4MIL (1oz)" at 12212.46,4090.92 h60
  text "2MIL (1.4oz)" at 12979.46,4090.92 h60
  text "2.8MIL (2oz)" at 13706.46,4090.92 h60
  text "OUTER:" at 11689.46,4086.64 h60
  text "X" at 13575,4085 h60
  text "1.4MIL (1oz)" at 12212.46,3933.92 h60
  text "2.8MIL (2oz)" at 12979.46,3933.92 h60
  text "N/A" at 13706,3934.29 h60
  text "INNER SIGNAL:" at 11400.38,3929.64 h60
  text "X" at 13575,3930 h60
  text "DRILLING:" at 11332.46,3790.64 h60
  text "REFERENCE:" at 11407.23,3673.64 h60
  text "X" at 12055.46,3673.64 h60
  text "AS SHOWN" at 12242.46,3673.64 h60
  text "X" at 12956.46,3673.64 h60
  text "NC_DRILL FILES" at 13093.46,3673.64 h60
  text "PTH MIN COPPER THICKNESS:" at 11407.23,3515.64 h60
  text "X" at 12757.46,3515.64 h60
  text "1MIL" at 12894.46,3515.64 h60
  text "OTHER" at 13391.46,3515.64 h60
  text "BOARD FINISH:" at 11332.46,3356.64 h60
  text "SILKSCREEN:" at 11487.68,3238.64 h60
  text "X" at 12436.46,3238.64 h60
  text "TOP" at 12562.46,3238.64 h60
  text "X" at 12946.46,3238.64 h60
  text "BOTTOM" at 13073.46,3238.64 h60
  text "SILKSCREEN COLOR:" at 11487.68,3071.64 h60
  text "X" at 12435.42,3071.64 h60
  text "WHITE" at 12562.46,3071.64 h60
  text "OTHER" at 13073.46,3071.64 h60
  text "SOLDER RESIST COLOR:" at 11487.68,2901.64 h60
  text "X" at 12055.42,2742.44 h60
  text "GREEN" at 12182.46,2742.44 h60
  text "BLUE" at 12773.46,2742.44 h60
  text "OTHER" at 13311.46,2742.44 h60
  text "IMMERSION GOLD (ENIG)" at 12393.46,2553.92 h60
  text "ENEPIG" at 13731,2550.64 h60
  text "SURFACE FINISH:" at 11332.46,2549.64 h60
  text "IMM. TIN/SILVER OR EQUIV" at 11662,2392.64 h60
  text "OTHER" at 13093.46,2392.64 h60
  text "X" at 11500,2390 h60
  text "ARRAY/PANEL:" at 11332.46,2213.64 h60
  text "CUT AND TRIM PER MECH LAYER 1" at 12393.46,2209.35 h60
  text "N.C. ROUTE" at 12393.46,2057.64 h60
  text "X" at 13072.46,2057.64 h60
  text "V. SCORE" at 13259.46,2057.64 h60
  text "CERTIFICATION:" at 11332.46,1920.64 h60
  text "MATERIALS AND WORKMANSHIP FOR ALL PCBS" at 12057.46,1920.64 h60
  text "TO MEET OR EXCEED THE REQUIREMENTS OF:" at 12057.46,1822.64 h60
  text "X" at 11683.96,1686.13 h60
  text "ANSI IPC-A-600F CLASS ->" at 11822.96,1686.13 h60
  text "X" at 13462.02,1686.13 h60
  text "2" at 13580.96,1686.14 h60
  text "1" at 13265.96,1684.64 h60
  text "3" at 13934.96,1684.64 h60
  text "X" at 11686.02,1526.64 h60
  text "UL 94V-0" at 11822.96,1526.64 h60
  text "X" at 12498.02,1526.64 h60
  text "RoHS" at 12634.96,1526.64 h60
  text "OTHER" at 13279.36,1526.64 h60
  text "PER ORDER" at 13676.42,1526.64 h60
  text "ADDITIONAL REQUIREMENTS:" at 11332.46,1385.64 h60
  text "MICROSECTION:" at 11407.23,1270.64 h60
  text "YES" at 12312.96,1270.64 h60
  text "REQUIRED" at 13174.46,1114.49 h60
  text "BARE BOARD ELEC. TEST:" at 11407.23,1111.64 h60
  text "NONE" at 12712.96,1111.64 h60
  text "X" at 13047.46,1111.64 h60
  text "PER ORDER" at 13766.46,1111.64 h60
  text "MANUFACTURER'S UL:" at 11407.23,954.64 h60
  text "RAIL" at 12572.96,950.35 h60
  text "METAL" at 13064.77,950.35 h60
  text "X" at 13440,950 h60
  text "SILK" at 13576.46,950.35 h60
  text ".Layer_Name" at 577,-858.49 h60
M11 Gerber Information:
  lines w10: -292,-930.17 6308,-930.17 ; -292,-726.83 6310,-726.83 ; -292,-523.5 -292,-1133.5 3713,-1133.5 6310,-1133.5 6310,-523.5 -291.5,-523.5 -291.5,-1133.5 1284,-1133.5 ; 2173,-1133.5 2173,-523.5 ; 3440,-726.83 3440,-523.5 ; 4280,-726.83 4280,-523.5 ; 4902,-1140 4902,-937.17
  text "ALL ARTWORK VIEWED FROM TOP SIDE" at -228.5,-655.67 h60
  text "BOARD #:" at 2248,-655.67 h60
  text ".PRJ_Number" at 2793.5,-655.67 h60
  text "REV:" at 3638,-655.67 h60
  text ".PCB_Rev" at 3929.5,-655.67 h60
  text "SVN REV:" at 4476,-655.67 h60
  text ".VersionControl_RevNumber" at 4982,-655.67 h60
  text "LAYER NAME =" at -228.5,-858.49 h60
  text "PLOT NAME =" at -228.5,-1064.34 h60
  text ".plot_File_Name" at 577,-1064.34 h60
  text "GENERATED    :" at 2250,-1064.34 h60
  text ".Print_Date" at 3119.5,-1064.34 h60
  text ".Print_Time" at 3848.5,-1064.34 h60
  text "TEXAS INSTRUMENTS" at 5113,-1064.34 h60
M12 Stackup:
  lines w6: 11360,7460 13910,7460 ; 11360,7564.4 13910,7564.4 ; 11300,6975 ccw(c11334,6975) 11334,6941 13936,6941 ccw(c13936,6975) 13970,6975 13970,7681 ccw(c13936,7681) 13936,7715 11334,7715 ccw(c11334,7681) 11300,7681 11300,6975
  text "The Stackup Legend below this is static." at 11605.5,7874.5 h60
  text "If you change the stackup, update the Legend." at 11615.5,7784.5 h60
  text "Layer Stack Up Detail for: Ref_Design.PcbDoc" at 11360,7597.1 h57
  text "Layer" at 11360,7525.4 h24
  text "Gerber" at 12255.81,7525.4 h24
  text "Copper" at 12819.33,7525.4 h24
  text "Dielectric" at 13422.04,7525.4 h24
  text "Name" at 11360,7477.4 h24
  text "Document" at 12255.81,7477.4 h24
  text "Thickness" at 12819.33,7477.4 h24
  text "Material" at 13422.04,7477.4 h24
  text "Top Solder Mask" at 11360,7384.44 h34
  text "(.GTS)" at 12255.81,7384.44 h34
  text "Solder Resist" at 13422.04,7384.44 h34
  text "Top Layer" at 11360,7287.69 h34
  text "(.GTL)" at 12255.81,7287.69 h34
  text "2.8mil" at 12819.33,7287.69 h34
  text "FR-4" at 13422.04,7239.31 h34
  text "Bottom Layer" at 11360,7190.94 h34
  text "(.GBL)" at 12255.81,7190.94 h34
  text "2.8mil" at 12819.33,7190.94 h34
  text "Bottom Solder Mask" at 11360,7094.19 h34
  text "(.GBS)" at 12255.81,7094.19 h34
  text "Solder Resist" at 13422.04,7094.19 h34
  text ".Layer_Name" at 577,-858.49 h60
M13 Component Bodies Top:
  text ".Layer_Name" at 577,-858.49 h60
M14 Component Bodies Bottom:
  text ".Layer_Name" at 577,-858.49 h60
M15 Courtyards Top:
  text ".Layer_Name" at 577,-858.49 h60
M16 Courtyards Bottom:
  text ".Layer_Name" at 577,-858.49 h60
Drill Drawing:
  text ".legend" at 3600,2135 h60
  text "Drill Table" at 3610,1975 h60
  text ".Layer_Name" at 577,-858.49 h60

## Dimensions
0,0 to 3500,0 on M2 Board Dimensions
0,0 to 0,2200 on M2 Board Dimensions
